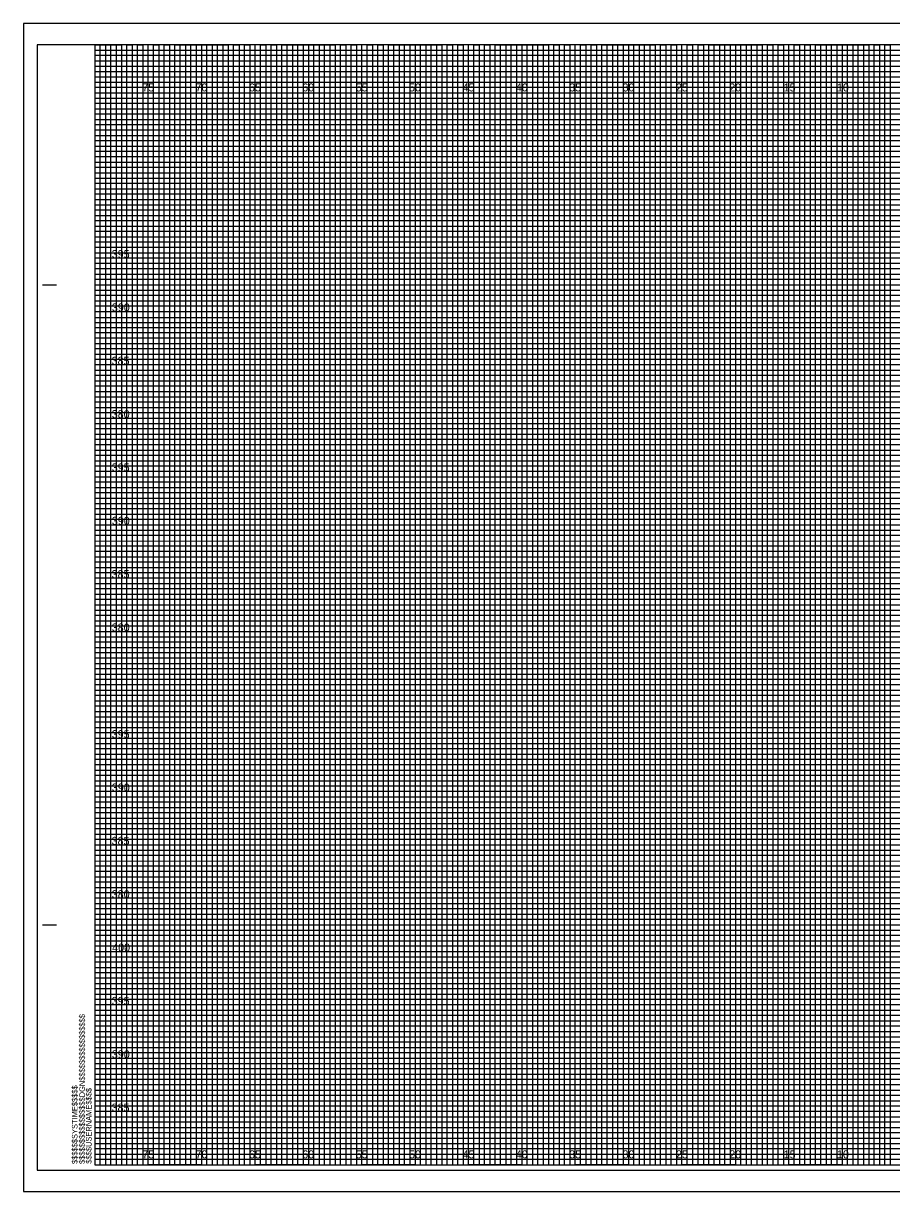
# Model space of a CAD drawing. Extents: x -7 to 162, y -2 to 217.
# Drawn here: x -6.7 to 74.6, y -2.5 to 107 of the extents above; entities that cross this region are included whole.
import ezdxf

# ---------------------------------------------------------------- set-up
doc = ezdxf.new("R2010")
doc.units = 0
for name, color, linetype in [('Exist Cross Section Cell', 7, 'Continuous'), ('Prop CMT Pvmt Course 2', 7, 'Continuous'), ('Prop CMT Pvmt Course 3', 7, 'Continuous'), ('Prop CMT Pvmt Surface Shoulder', 7, 'Continuous'), ('Prop CMT Shld Paved Course 1', 7, 'Continuous'), ('Prop CMT Shld Paved Course 2', 7, 'Continuous'), ('Prop CMT Shld Paved Course 3', 7, 'Continuous'), ('Prop CMT Subgrade Earthwork', 7, 'Continuous'), ('Scratch_Level_3', 7, 'Continuous')]:
    doc.layers.add(name, color=color, linetype=linetype)

msp = doc.modelspace()

# ---------------------------------------------------------------- linework, layer by layer
at = {"layer": 'Prop CMT Pvmt Course 2'}
for p, q in [((0, 104.5), (110.95, 104.5)), ((110.95, 103.99), (0, 103.99)), ((0, 103.99), (0, 103.5)), ((0, 103.5), (110.95, 103.5)), ((110.95, 102.95), (0, 102.95)), ((0, 102.95), (0, 102)), ((0, 102), (160, 102))]:
    msp.add_line(p, q, dxfattribs=at)
for points in [[(0, 101.5), (135, 101.5), (160, 101.5)], [(160, 101), (0, 101)], [(0, 100.5), (160, 100.5)], [(160, 99.5), (0, 99.5)], [(0, 99), (160, 99)], [(160, 98.5), (0, 98.49)], [(0, 98), (160, 98)], [(160, 97), (0, 97)], [(0, 96.5), (160, 96.5), (160, 96), (0, 96)], [(0, 95.5), (160, 95.5), (160, 94.5), (0, 94.5)], [(0, 94), (160, 94), (160, 93.5), (0, 93.5)], [(0, 93), (160, 93), (160, 92), (0, 92)], [(0, 91.5), (160, 91.5), (160, 91), (0, 91)], [(0, 90.5), (160, 90.5), (160, 89.5), (0, 89.5)], [(0, 89), (160, 89), (160, 88.5), (0, 88.5)], [(0, 88), (160, 88), (160, 86.97), (160, 86.5), (160, 86), (0, 86)], [(0, 87), (160, 87), (160, 86.5), (0, 86.5)], [(0, 85.5), (160, 85.5), (160, 84.5), (0, 84.51)], [(0, 84.51), (160, 84.5), (160, 84), (0, 84)], [(0, 83.5), (160, 83.5), (160, 83), (0, 83)], [(0, 82), (160, 82), (160, 81.5), (0, 81.5)], [(0, 81), (160, 81), (160, 80.5), (0, 80.5)], [(-0.04, 79.44), (160, 79.44), (160, 78.94), (-0.04, 78.94)], [(0, 78.5), (160, 78.5), (160, 78), (0, 78)], [(0, 77), (160, 77), (160, 76.5), (0, 76.5)], [(0, 76), (160, 76), (160, 75.5), (0, 75.5)], [(0, 74.5), (160, 74.5), (160, 74), (0, 74)], [(0, 73.5), (160, 73.5), (160, 73), (0, 73)], [(0, 72), (160, 72), (160, 71.5), (0, 71.5)], [(0, 71), (160, 71), (160, 70.5), (0, 70.5)], [(0, 69.5), (160, 69.5), (159.99, 68.99), (0, 69)], [(0, 68.5), (160, 68.5), (160, 68), (0, 68)], [(0, 67), (160, 67), (160, 66.5), (0, 66.5)], [(0, 66), (160, 66), (160, 65.5), (0, 65.5)], [(0, 64.5), (160, 64.5), (160, 64), (0, 64)], [(0, 63.5), (160, 63.5), (160, 63), (0, 63)], [(0, 62), (160, 62), (160, 61.5), (0, 61.5)], [(0, 61), (160, 61), (160, 60.5), (0, 60.5)], [(0, 59.5), (160, 59.5), (160, 59), (0, 59)], [(0, 58.5), (160.03, 58.45), (160, 58), (0, 58)], [(0, 57), (160, 57), (160, 56.5), (0, 56.5)], [(0, 56), (160, 56), (160, 55.5), (0, 55.5)], [(0, 54.5), (160, 54.5), (160, 54), (0, 54)], [(0, 53.5), (160, 53.5), (160, 53), (0, 53)], [(0, 52), (160, 52), (160, 51.5), (0, 51.5)], [(0, 51), (160, 51), (160, 50.5), (0, 50.5)], [(0, 49.5), (160, 49.5), (160, 49), (0, 49)], [(0, 48.5), (160, 48.5), (160, 48), (0, 48)], [(0, 47), (160, 47), (160, 46.5), (0, 46.5)], [(0, 46), (160, 46), (160, 45.5), (0, 45.5)], [(0, 44.5), (160, 44.5), (160, 44), (0, 44)], [(0, 43.5), (160, 43.5), (160, 43), (0, 43)], [(0, 42), (160, 42), (160, 41.5), (0, 41.5)], [(0, 41), (160, 41), (160, 40.5), (0, 40.5)], [(0, 39.5), (160, 39.5), (159.99, 38.99), (0, 39)], [(0, 38.5), (160, 38.5), (160, 38), (0, 38)], [(0, 37), (160, 37), (160, 36.5), (0, 36.5)], [(0, 36), (160, 36), (160, 35.5), (0, 35.5)], [(0, 34.5), (160, 34.5), (160, 34), (0, 34)], [(0, 33.5), (160, 33.5), (160, 33), (0, 33)], [(0, 32), (160, 32), (160, 31.5), (0, 31.5)], [(0, 31), (160, 31), (160, 30.5), (0, 30.5)], [(0, 29.5), (160, 29.5), (160, 29), (0, 29)], [(0, 28.5), (160.03, 28.46), (160, 28), (0, 28)], [(0, 27), (160, 27), (160, 26.5), (0, 26.5)], [(0, 26), (160, 26), (160, 25.5), (0, 25.5)], [(0, 24.5), (160, 24.5), (160, 24), (0, 24)], [(0, 23.5), (160, 23.5), (160, 23), (0, 23)], [(0, 22), (160, 22), (160, 21.5), (0, 21.5)], [(0, 21), (160, 21), (160, 20.5), (0, 20.5)], [(0, 19.5), (160, 19.5), (160, 19), (0, 19)], [(0, 18.5), (160, 18.5), (160, 18), (0, 18)], [(0, 17), (160, 17), (160, 16.5), (0, 16.5)], [(0, 16), (160, 16), (160, 15.5), (0, 15.5)], [(0, 14.5), (160, 14.5), (160, 14), (0, 14)], [(0, 13.5), (160, 13.5), (160, 13), (0, 13)], [(0, 12), (160, 12), (160, 11.5), (0, 11.5)], [(0, 11), (160, 11), (160, 10.5), (0, 10.5)], [(0, 9.5), (160, 9.5), (160, 9), (0, 9)], [(0, 8.5), (160, 8.5), (160, 8), (0, 8)], [(0, 7), (160, 7), (160, 6.5), (0, 6.5)], [(0, 6), (160, 6), (160, 5.5), (0, 5.5)], [(0, 4.5), (160, 4.5), (160, 4), (0, 4)], [(0, 3.5), (160, 3.5), (160, 3), (0, 3)], [(0, 2), (160, 2), (160, 1.5), (0, 1.5)], [(0, 1), (160, 1), (160, 0.5), (0, 0.5)]]:
    msp.add_lwpolyline(points, dxfattribs=at)
at = {"layer": 'Prop CMT Pvmt Course 3'}
for p, q in [((5, 105), (0, 105)), ((5, 0), (5, 105)), ((15, 105), (10, 105)), ((10, 105), (10, 0)), ((15, 0), (15, 105)), ((25, 105), (20, 105)), ((20, 105), (20, 0)), ((25, 0), (25, 105)), ((35, 105), (30, 105)), ((30, 105), (30, 0)), ((35, 0), (35, 105)), ((45, 105), (40, 105)), ((40, 105), (40, 0)), ((45, 0), (45, 105)), ((55, 105), (50, 105)), ((50, 105), (50, 0)), ((55, 0), (55, 105)), ((65, 105), (60, 105)), ((60, 105), (60, 0)), ((65, 0), (65, 105)), ((75, 105), (70, 105)), ((70, 105), (70, 0)), ((10, 0), (5, 0)), ((20, 0), (15, 0)), ((30, 0), (25, 0)), ((40, 0), (35, 0)), ((60, 0), (55, 0)), ((70, 0), (65, 0)), ((50, 0), (45, 0))]:
    msp.add_line(p, q, dxfattribs=at)
for points in [[(160, 102.5), (160, 95), (0, 95)], [(0, 100), (160, 100)], [(0, 90), (160, 90), (160, 85), (0, 85)], [(0, 80), (160, 80), (160, 75), (0, 75)], [(0, 70), (160, 70), (160, 65), (0, 65)], [(0, 60), (160, 60), (160, 55), (0, 55)], [(0, 50), (160, 50), (160, 45), (0, 45)], [(0, 40), (160, 40), (160, 35), (0, 35)], [(0, 30), (160, 30), (160, 25), (0, 25)], [(0, 20), (160, 20), (160, 15), (0, 15)], [(0, 10), (160, 10), (160, 5), (0, 5)]]:
    msp.add_lwpolyline(points, dxfattribs=at)
at = {"layer": 'Prop CMT Shld Paved Course 1'}
msp.add_lwpolyline([(-6.7, -2.5), (161.65, -2.5), (161.65, 107), (-6.7, 107)], close=True, dxfattribs=at)
at = {"layer": 'Prop CMT Shld Paved Course 2'}
msp.add_lwpolyline([(-5.4, -0.5), (161.2, -0.5), (161.2, 105), (-5.4, 105)], close=True, dxfattribs=at)
at = {"layer": 'Prop CMT Shld Paved Course 3'}
for points in [[(0, 105), (2.5, 105), (2.5, 0), (7.5, 0), (7.5, 105), (12.5, 105), (12.5, 0), (17.5, 0), (17.5, 105), (22.5, 105), (22.5, 0), (27.5, 0), (27.5, 105), (32.5, 105), (32.5, 0), (37.5, 0), (37.5, 105), (42.5, 105), (42.5, 0), (47.5, 0), (47.5, 105), (52.5, 105), (52.5, 0), (57.5, 0), (57.5, 105), (62.5, 105), (62.5, 0), (67.5, 0), (67.5, 105), (72.5, 105), (72.5, 0), (77.5, 0)], [(0, 102.5), (137.5, 102.5)], [(0, 92.5), (160, 92.5), (160, 102.5)], [(160, 97.5), (0, 97.5)], [(0, 82.5), (160, 82.5), (160, 87.5), (0, 87.5)], [(0, 72.5), (160, 72.5), (160, 77.5), (0, 77.5)], [(0, 62.5), (160, 62.5), (160, 67.5), (0, 67.5)], [(0, 52.5), (160, 52.5), (160, 57.5), (0, 57.5)], [(0, 42.5), (160, 42.5), (160, 47.5), (0, 47.5)], [(0, 32.5), (160, 32.5), (160, 37.5), (0, 37.5)], [(0, 22.5), (160, 22.5), (160, 27.5), (0, 27.5)], [(0, 12.5), (160, 12.5), (160, 17.5), (0, 17.5)], [(0, 2.5), (160, 2.5), (160, 7.5), (0, 7.5)]]:
    msp.add_lwpolyline(points, dxfattribs=at)
at = {"layer": 'Prop CMT Subgrade Earthwork'}
for points in [[(0, 0), (0.5, 0), (0.5, 105), (1, 105), (1, 0)], [(1, 0), (1.5, 0), (1.5, 105), (2, 105), (2, 0)], [(2.5, 0), (3, 0), (3, 105), (3.5, 105), (3.5, 0)], [(3.5, 0), (4, 0), (4, 105), (4.5, 105), (4.5, 0)], [(5, 0), (5.5, 0), (5.5, 105), (6, 105), (6, 0)], [(6, 0), (6.5, 0), (6.5, 105), (7, 105), (7, 0)], [(7.5, 0), (8, 0), (8, 105), (8.5, 105), (8.5, 0)], [(8.5, 0), (9, 0), (9, 105), (9.5, 105), (9.5, 0)], [(10, 0), (10.5, 0), (10.5, 105), (11, 105), (11, 0)], [(11, 0), (11.5, 0), (11.5, 105), (12, 105), (12, 0)], [(12.5, 0), (13, 0), (13, 105), (13.5, 105), (13.5, 0)], [(13.5, 0), (14, 0), (14, 105), (14.5, 105), (14.5, 0)], [(15, 0), (15.5, 0), (15.5, 105), (16, 105), (16, 0)], [(16, 0), (16.5, 0), (16.5, 105), (17, 105), (17, 0)], [(17.5, 0), (18, 0), (18, 105), (18.5, 105), (18.5, 0)], [(18.5, 0), (19, 0), (19, 105), (19.5, 105), (19.5, 0)], [(20, 0), (20.5, 0), (20.5, 105), (21, 105), (21, 0)], [(21, 0), (21.5, 0), (21.5, 105), (22, 105), (22, 0)], [(22.5, 0), (23, 0), (23, 105), (23.5, 105), (23.5, 0)], [(23.5, 0), (24, 0), (24, 105), (24.5, 105), (24.5, 0)], [(25, 0), (25.5, 0), (25.5, 105), (26, 105), (26, 0)], [(26, 0), (26.5, 0), (26.5, 105), (27, 105), (27, 0)], [(27.5, 0), (28, 0), (28, 105), (28.5, 105), (28.5, 0)], [(28.5, 0), (29, 0), (29, 105), (29.5, 105), (29.5, 0)], [(30, 0), (30.5, 0), (30.5, 105), (31, 105), (31, 0)], [(31, 0), (31.5, 0), (31.5, 105), (32, 105), (32, 0)], [(32.5, 0), (33, 0), (33, 105), (33.5, 105), (33.5, 0)], [(33.5, 0), (34, 0), (34, 105), (34.5, 105), (34.5, 0)], [(35, 0), (35.5, 0), (35.5, 105), (36, 105), (36, 0)], [(36, 0), (36.5, 0), (36.5, 105), (37, 105), (37, 0)], [(37.5, 0), (38, 0), (38, 105), (38.5, 105), (38.5, 0)], [(38.5, 0), (39, 0), (39, 105), (39.5, 105), (39.5, 0)], [(40, 0), (40.5, 0), (40.5, 105), (41, 105), (41, 0)], [(41, 0), (41.5, 0), (41.5, 105), (42, 105), (42, 0)], [(42.5, 0), (43, 0), (43, 105), (43.5, 105), (43.5, 0)], [(43.5, 0), (44, 0), (44, 105), (44.5, 105), (44.5, 0)], [(45, 0), (45.5, 0), (45.5, 105), (46, 105), (46, 0)], [(46, 0), (46.5, 0), (46.5, 105), (47, 105), (47, 0)], [(47.5, 0), (48, 0), (48, 105), (48.5, 105), (48.5, 0)], [(48.5, 0), (49, 0), (49, 105), (49.5, 105), (49.5, 0)], [(50, 0), (50.5, 0), (50.5, 105), (51, 105), (51, 0)], [(51, 0), (51.5, 0), (51.5, 105), (52, 105), (52, 0)], [(52.5, 0), (53, 0), (53, 105), (53.5, 105), (53.5, 0)], [(53.5, 0), (54, 0), (54, 105), (54.5, 105), (54.5, 0)], [(55, 0), (55.5, 0), (55.5, 105), (56, 105), (56, 0)], [(56, 0), (56.5, 0), (56.5, 105), (57, 105), (57, 0)], [(57.5, 0), (58, 0), (58, 105), (58.5, 105), (58.5, 0)], [(58.5, 0), (59, 0), (59, 105), (59.5, 105), (59.5, 0)], [(60, 0), (60.5, 0), (60.5, 105), (61, 105), (61, 0)], [(61, 0), (61.5, 0), (61.5, 105), (62, 105), (62, 0)], [(62.5, 0), (63, 0), (63, 105), (63.5, 105), (63.5, 0)], [(63.5, 0), (64, 0), (64, 105), (64.5, 105), (64.5, 0)], [(65, 0), (65.5, 0), (65.5, 105), (66, 105), (66, 0)], [(66, 0), (66.5, 0), (66.5, 105), (67, 105), (67, 0)], [(67.5, 0), (68, 0), (68, 105), (68.5, 105), (68.5, 0)], [(68.5, 0), (69, 0), (69, 105), (69.5, 105), (69.5, 0)], [(70, 0), (70.5, 0), (70.5, 105), (71, 105), (71, 0)], [(71, 0), (71.5, 0), (71.5, 105), (72, 105), (72, 0)], [(72.5, 0), (73, 0), (73, 105), (73.5, 105), (73.5, 0)], [(73.5, 0), (74, 0), (74, 105), (74.5, 105), (74.5, 0)]]:
    msp.add_lwpolyline(points, dxfattribs=at)
at = {"layer": 'Scratch_Level_3'}
for p, q in [((-4.9, 82.5), (-3.65, 82.5)), ((-4.85, 82.5), (-3.6, 82.5)), ((-4.9, 22.5), (-3.65, 22.5)), ((-4.85, 22.5), (-3.6, 22.5)), ((0, 0), (0, 0)), ((0, 0), (0, 0)), ((0, 0), (0, 0)), ((0, 0), (0, 0)), ((0, 0), (0, 0)), ((0, 0), (0, 0)), ((0, 0), (0, 0))]:
    msp.add_line(p, q, dxfattribs=at)
msp.add_lwpolyline([(160, 105), (0, 105), (0, 0), (160, 0)], close=True, dxfattribs=at)

# ---------------------------------------------------------------- texts
at = {"layer": 'Exist Cross Section Cell'}
for s, p in [('75', (4.44, 100.62)), ('70', (9.43, 100.62)), ('65', (14.44, 100.62)), ('60', (19.43, 100.62)), ('55', (24.44, 100.62)), ('50', (29.43, 100.62)), ('45', (34.44, 100.62)), ('40', (39.43, 100.62)), ('35', (44.44, 100.62)), ('30', (49.43, 100.62)), ('25', (54.44, 100.62)), ('20', (59.43, 100.62)), ('15', (64.53, 100.62)), ('10', (69.52, 100.62)), ('75', (4.44, 0.62)), ('70', (9.43, 0.62)), ('65', (14.44, 0.62)), ('60', (19.43, 0.62)), ('55', (24.44, 0.62)), ('50', (29.43, 0.62)), ('45', (34.44, 0.62)), ('40', (39.43, 0.62)), ('35', (44.44, 0.62)), ('30', (49.43, 0.62)), ('25', (54.44, 0.62)), ('20', (59.43, 0.62)), ('15', (64.53, 0.62)), ('10', (69.52, 0.62))]:
    msp.add_text(s, height=0.75, dxfattribs=at).set_placement(p)
at = {"layer": 'Prop CMT Pvmt Surface Shoulder'}
for s, p in [('395', (1.58, 85)), ('390', (1.59, 80)), ('385', (1.57, 75)), ('380', (1.58, 70)), ('395', (1.58, 65)), ('390', (1.59, 60)), ('385', (1.57, 55)), ('380', (1.58, 50)), ('395', (1.58, 40)), ('390', (1.59, 35)), ('385', (1.57, 30)), ('380', (1.58, 25)), ('400', (1.62, 20)), ('395', (1.58, 15)), ('390', (1.59, 10)), ('385', (1.57, 5))]:
    msp.add_text(s, height=0.75, dxfattribs=at).set_placement(p)
at = {"layer": 'Scratch_Level_3'}
for s, p in [('$$$$$$$$$$$$$$$$DGN$$$$$$$$$$$$$$$$', (-0.94, 0.09)), ('$$$$$$SYSTIME$$$$$', (-1.63, 0.09)), ('$$$$USERNAME$$$$', (-0.31, 0.12))]:
    msp.add_text(s, height=0.525, rotation=90, dxfattribs=at).set_placement(p)

doc.saveas('drawing.dxf')
